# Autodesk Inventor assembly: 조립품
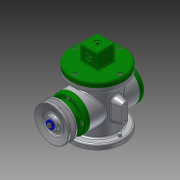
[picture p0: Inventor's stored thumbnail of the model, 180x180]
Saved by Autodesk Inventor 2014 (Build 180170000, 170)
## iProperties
Created: 2018-02
Part Number: 조립품
Document SubType Name: Assembly
Designer: OA65
Author: OA65
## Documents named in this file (18)
- C:\Users\OA65\Desktop\480208V1010\조립품.iam
- C:\Users\OA65\Desktop\480208V1010\본체.ipt
- C:\Users\OA65\Desktop\480208V1010\덮개.ipt
- C:\Users\OA65\Desktop\480208V1010\앞커버.ipt
- C:\Users\OA65\Desktop\480208V1010\뒤커버.ipt
- C:\Users\OA65\Desktop\480208V1010\베어링 17 x 40 x 12.ipt
- C:\Users\OA65\Desktop\480208V1010\편심축.ipt
- C:\Users\OA65\Desktop\480208V1010\링크.ipt
- C:\Users\OA65\Desktop\480208V1010\슬라이더.ipt
- C:\Users\OA65\Desktop\480208V1010\클레비스 핀 6 x 22.ipt
- 클레비스 핀 6 x 22.ipt
- C:\Users\OA65\Desktop\480208V1010\E-링.ipt
- C:\Users\OA65\Desktop\480208V1010\오일 실 17 30 8.ipt
- C:\Users\OA65\Desktop\480208V1010\키 4 x 4 x 12.ipt
- C:\Users\OA65\Desktop\480208V1010\V-벨트풀리.ipt
- C:\Users\OA65\Desktop\480208V1010\와셔 4x16.ipt
- C:\Users\OA65\Desktop\480208V1010\볼트 M4 x 10.ipt
- C:\Users\OA65\Desktop\480208V1010\볼트 M4 x 8.ipt
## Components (2 placed, 2 different names)
1. E-링:1
2. V-벨트풀리:1 — 각도:2
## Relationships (1: Angle 1)
- 각도:2 [Angle]: V-벨트풀리:1
